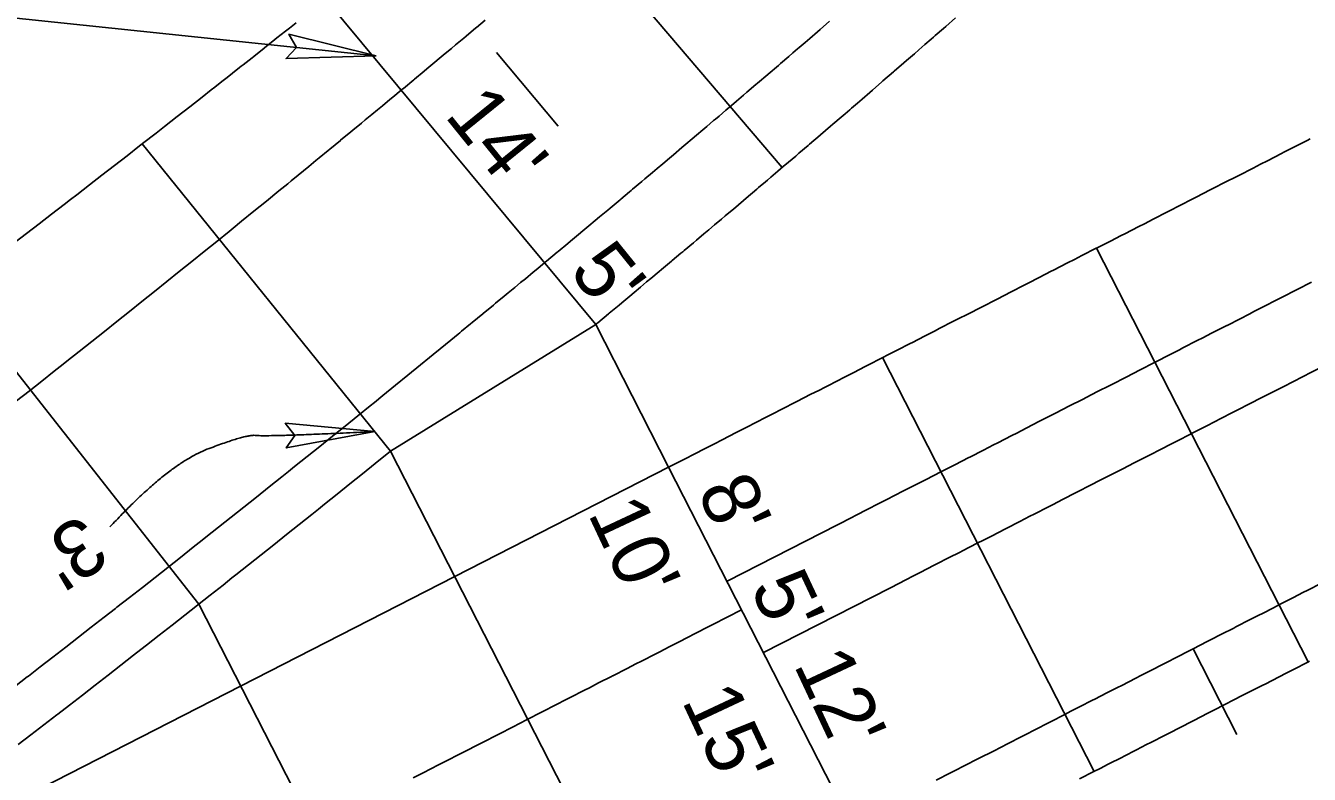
# Model space of a CAD drawing. Extents: x 2145147 to 2158018, y 137519 to 148068.
# Drawn here: x 2149836.3 to 2149916.4, y 143287.3 to 143334 of the extents above; entities that cross this region are included whole.
import ezdxf

# ---------------------------------------------------------------- set-up
doc = ezdxf.new("R2010")
doc.units = 0
for name, color, linetype in [('PR_Align_Ramp_A', 7, 'Continuous'), ('PR_Align_Ramp_F', 7, 'Continuous'), ('PR_Align_Service_C_Leader', 7, 'Continuous'), ('PR_Arrows', 7, 'Continuous'), ('PR_Dimensions', 7, 'Continuous'), ('PR_Joint_Contraction', 7, 'Continuous'), ('PR_Joint_Isolation', 7, 'Continuous'), ('PR_Joint_Long', 7, 'Continuous'), ('PR_Road_Concrete', 7, 'Continuous')]:
    doc.layers.add(name, color=color, linetype=linetype)

msp = doc.modelspace()

# ---------------------------------------------------------------- linework, layer by layer
at = {"layer": 'PR_Align_Ramp_A'}
msp.add_lwpolyline([(2149911.878, 143289.817), (2149909.145, 143295.159)], dxfattribs=at)
at = {"layer": 'PR_Align_Ramp_F'}
msp.add_lwpolyline([(2149869.527, 143327.778), (2149865.671, 143332.374)], dxfattribs=at)
at = {"layer": 'PR_Align_Service_C_Leader'}
msp.add_lwpolyline([(2149858.151, 143332.151), (2149826.935, 143335.418), (2149798.151, 143316.453)], dxfattribs=at)
at = {"layer": 'PR_Arrows'}
msp.add_lwpolyline([(2149858.151, 143332.151), (2149852.539, 143331.986), (2149853.191, 143332.67), (2149852.708, 143333.509)], close=True, dxfattribs=at)
at = {"layer": 'PR_Dimensions'}
msp.add_lwpolyline([(2149858.07, 143308.712), (2149852.548, 143307.7), (2149853.089, 143308.476), (2149852.484, 143309.232)], close=True, dxfattribs=at)
msp.add_open_spline([(2149841.542, 143302.766), (2149845.177, 143306.681), (2149850.08, 143308.559), (2149851.247, 143308.388), (2149858.07, 143308.712)], degree=2, dxfattribs=at)
at = {"layer": 'PR_Joint_Contraction'}
for p, q in [((2149883.51, 143325.197), (2149866.572, 143345.068)), ((2149859.056, 143307.493), (2149843.557, 143326.662)), ((2149903.123, 143320.16), (2149916.331, 143294.343)), ((2149847.09, 143297.948), (2149831.675, 143317.535)), ((2149889.769, 143313.328), (2149902.978, 143287.511)), ((2149859.056, 143307.493), (2149876.27, 143273.847)), ((2149847.09, 143297.948), (2149862.916, 143267.015))]:
    msp.add_line(p, q, dxfattribs=at)
at = {"layer": 'PR_Joint_Isolation'}
for p, q in [((2149871.861, 143315.398), (2149855.01, 143335.699)), ((2149876.415, 143306.496), (2149889.624, 143280.679))]:
    msp.add_line(p, q, dxfattribs=at)
at = {"layer": 'PR_Joint_Long'}
msp.add_line((2149876.415, 143306.497), (2149836.353, 143286.001), dxfattribs=at)
for points in [[(2149886.46, 143334.319), (2149885.872, 143333.811), (2149885.695, 143333.658), (2149885.22, 143333.248), (2149884.931, 143332.999), (2149884.568, 143332.687), (2149884.453, 143332.588), (2149884.165, 143332.34), (2149883.915, 143332.125), (2149883.4, 143331.682), (2149883.261, 143331.563), (2149882.633, 143331.025), (2149882.608, 143331.003), (2149881.957, 143330.446), (2149881.863, 143330.365), (2149881.303, 143329.886), (2149881.096, 143329.709), (2149880.648, 143329.327), (2149880.327, 143329.054), (2149879.992, 143328.768), (2149879.559, 143328.399), (2149879.338, 143328.211), (2149879.223, 143328.114), (2149878.789, 143327.745), (2149878.68, 143327.652), (2149878.027, 143327.098), (2149878.016, 143327.089), (2149877.37, 143326.542), (2149877.246, 143326.436), (2149876.713, 143325.985), (2149876.475, 143325.784), (2149876.055, 143325.429), (2149875.704, 143325.133), (2149875.397, 143324.874), (2149874.931, 143324.482), (2149874.738, 143324.319), (2149874.159, 143323.832), (2149874.08, 143323.766), (2149873.967, 143323.671), (2149873.423, 143323.214), (2149873.382, 143323.18), (2149872.763, 143322.661), (2149872.608, 143322.531), (2149872.103, 143322.108), (2149871.834, 143321.883), (2149871.442, 143321.556), (2149871.059, 143321.236), (2149870.781, 143321.004), (2149870.284, 143320.589), (2149870.119, 143320.452), (2149869.508, 143319.944), (2149869.457, 143319.902), (2149868.799, 143319.354), (2149868.729, 143319.297), (2149868.666, 143319.244), (2149868.136, 143318.804), (2149867.95, 143318.651), (2149867.473, 143318.255), (2149867.173, 143318.007), (2149866.809, 143317.706), (2149866.394, 143317.364), (2149866.145, 143317.158), (2149865.616, 143316.721), (2149865.48, 143316.61), (2149864.836, 143316.079), (2149864.816, 143316.063), (2149864.154, 143315.519), (2149864.053, 143315.435), (2149863.489, 143314.972), (2149863.377, 143314.881), (2149863.272, 143314.795), (2149862.822, 143314.426), (2149862.491, 143314.155), (2149862.156, 143313.881), (2149861.709, 143313.516), (2149861.489, 143313.336), (2149860.925, 143312.876), (2149860.143, 143312.238), (2149859.359, 143311.6), (2149858.575, 143310.964), (2149858.044, 143310.533), (2149857.788, 143310.326), (2149857.004, 143309.692), (2149856.217, 143309.057), (2149855.431, 143308.423), (2149854.644, 143307.789), (2149853.856, 143307.157), (2149853.068, 143306.525), (2149852.683, 143306.217), (2149852.277, 143305.892), (2149851.489, 143305.262), (2149850.699, 143304.632), (2149849.908, 143304.003), (2149849.117, 143303.374), (2149848.326, 143302.746), (2149847.535, 143302.12), (2149847.296, 143301.932), (2149846.74, 143301.492), (2149845.947, 143300.867), (2149845.154, 143300.241), (2149844.359, 143299.617), (2149843.564, 143298.993), (2149842.769, 143298.37), (2149841.975, 143297.749), (2149841.885, 143297.679), (2149841.176, 143297.126), (2149840.379, 143296.505), (2149839.581, 143295.885), (2149838.783, 143295.265), (2149837.985, 143294.646), (2149837.185, 143294.028), (2149836.452, 143293.461), (2149836.384, 143293.409), (2149835.585, 143292.793)], [(2149864.963, 143334.391), (2149864.422, 143333.937), (2149864.385, 143333.907), (2149863.771, 143333.391), (2149863.62, 143333.265), (2149863.119, 143332.846), (2149862.855, 143332.624), (2149862.467, 143332.3), (2149862.088, 143331.984), (2149861.814, 143331.756), (2149861.322, 143331.345), (2149861.161, 143331.212), (2149860.554, 143330.706), (2149860.508, 143330.668), (2149859.854, 143330.124), (2149859.787, 143330.069), (2149859.725, 143330.018), (2149859.2, 143329.581), (2149859.018, 143329.431), (2149858.545, 143329.039), (2149858.249, 143328.795), (2149857.89, 143328.498), (2149857.48, 143328.159), (2149857.235, 143327.956), (2149856.71, 143327.523), (2149856.579, 143327.416), (2149855.939, 143326.889), (2149855.923, 143326.875), (2149855.266, 143326.335), (2149855.168, 143326.255), (2149854.609, 143325.796), (2149854.5, 143325.706), (2149854.397, 143325.622), (2149853.951, 143325.257), (2149853.624, 143324.989), (2149853.293, 143324.718), (2149852.851, 143324.357), (2149852.635, 143324.181), (2149852.078, 143323.726), (2149851.304, 143323.095), (2149850.53, 143322.466), (2149849.755, 143321.836), (2149849.23, 143321.411), (2149848.979, 143321.208), (2149848.203, 143320.58), (2149847.426, 143319.953), (2149846.649, 143319.326), (2149845.872, 143318.7), (2149845.093, 143318.075), (2149844.314, 143317.451), (2149843.935, 143317.147), (2149843.535, 143316.827), (2149842.755, 143316.204), (2149841.975, 143315.582), (2149841.194, 143314.96), (2149840.412, 143314.339), (2149839.63, 143313.718), (2149838.847, 143313.099), (2149838.614, 143312.914), (2149838.064, 143312.48), (2149837.281, 143311.861), (2149836.496, 143311.244), (2149835.712, 143310.627)], [(2149916.536, 143318.036), (2149915.648, 143317.581), (2149915.561, 143317.537), (2149914.754, 143317.124), (2149914.094, 143316.786), (2149913.862, 143316.667), (2149912.983, 143316.218), (2149912.653, 143316.05), (2149912.083, 143315.757), (2149911.273, 143315.343), (2149911.261, 143315.337), (2149910.306, 143314.848), (2149909.752, 143314.565), (2149909.412, 143314.391), (2149908.513, 143313.931), (2149908.295, 143313.819), (2149907.642, 143313.485), (2149906.858, 143313.084), (2149906.75, 143313.03), (2149905.854, 143312.57), (2149905.406, 143312.341), (2149904.966, 143312.117), (2149904.07, 143311.658), (2149903.946, 143311.594), (2149903.186, 143311.206), (2149902.47, 143310.84), (2149902.278, 143310.74), (2149901.403, 143310.294), (2149901.03, 143310.103), (2149900.51, 143309.836), (2149899.608, 143309.375), (2149899.571, 143309.356), (2149898.73, 143308.926), (2149898.143, 143308.625), (2149897.845, 143308.473), (2149896.96, 143308.02), (2149896.695, 143307.885), (2149896.059, 143307.559), (2149895.206, 143307.123), (2149895.145, 143307.092), (2149894.28, 143306.649), (2149893.786, 143306.396), (2149893.394, 143306.196), (2149892.478, 143305.727), (2149892.322, 143305.647), (2149891.616, 143305.287), (2149890.867, 143304.903), (2149890.715, 143304.825), (2149889.827, 143304.371), (2149889.416, 143304.161), (2149888.94, 143303.917), (2149888.004, 143303.439), (2149887.923, 143303.397), (2149880.059, 143299.373)], [(2149871.861, 143315.398), (2149859.056, 143307.493), (2149858.101, 143306.722), (2149857.312, 143306.086), (2149856.523, 143305.451), (2149855.733, 143304.817), (2149854.943, 143304.183), (2149854.557, 143303.874), (2149854.152, 143303.55), (2149853.361, 143302.918), (2149852.568, 143302.286), (2149851.776, 143301.655), (2149850.983, 143301.025), (2149850.189, 143300.395), (2149849.395, 143299.766), (2149849.158, 143299.579), (2149848.6, 143299.138), (2149847.805, 143298.511), (2149847.009, 143297.884), (2149846.212, 143297.258), (2149845.415, 143296.632), (2149844.618, 143296.008), (2149843.82, 143295.383), (2149843.733, 143295.316), (2149843.021, 143294.76), (2149842.222, 143294.137), (2149841.422, 143293.516), (2149840.622, 143292.894), (2149839.821, 143292.274), (2149839.02, 143291.654), (2149838.282, 143291.085), (2149838.218, 143291.035), (2149837.415, 143290.416), (2149836.612, 143289.799), (2149835.809, 143289.182)], [(2149917.032, 143312.673), (2149916.374, 143312.336), (2149916.141, 143312.217), (2149915.258, 143311.766), (2149914.931, 143311.598), (2149914.361, 143311.306), (2149913.529, 143310.881), (2149913.519, 143310.876), (2149912.583, 143310.396), (2149912.028, 143310.113), (2149911.69, 143309.94), (2149910.794, 143309.481), (2149910.573, 143309.368), (2149909.917, 143309.033), (2149909.132, 143308.631), (2149909.026, 143308.577), (2149908.131, 143308.119), (2149907.68, 143307.888), (2149907.242, 143307.665), (2149906.348, 143307.207), (2149906.222, 143307.142), (2149905.462, 143306.754), (2149904.754, 143306.392), (2149904.559, 143306.291), (2149903.68, 143305.842), (2149903.31, 143305.653), (2149902.788, 143305.385), (2149901.89, 143304.926), (2149901.853, 143304.907), (2149901.008, 143304.475), (2149900.418, 143304.173), (2149900.121, 143304.021), (2149899.235, 143303.567), (2149898.969, 143303.432), (2149898.337, 143303.108), (2149897.491, 143302.676), (2149897.43, 143302.644), (2149896.557, 143302.198), (2149896.062, 143301.944), (2149895.67, 143301.744), (2149894.762, 143301.279), (2149894.602, 143301.197), (2149893.892, 143300.835), (2149893.147, 143300.453), (2149892.994, 143300.375), (2149892.105, 143299.92), (2149891.696, 143299.711), (2149891.217, 143299.466), (2149890.294, 143298.994), (2149890.215, 143298.953), (2149882.337, 143294.922)], [(2149917.158, 143299.258), (2149916.267, 143298.802), (2149916.041, 143298.686), (2149915.377, 143298.347), (2149914.589, 143297.944), (2149914.487, 143297.892), (2149913.597, 143297.436), (2149913.137, 143297.201), (2149912.706, 143296.981), (2149911.816, 143296.525), (2149911.685, 143296.458), (2149910.926, 143296.07), (2149910.234, 143295.716), (2149910.036, 143295.614), (2149909.145, 143295.159), (2149908.782, 143294.973), (2149908.255, 143294.703), (2149907.365, 143294.248), (2149907.33, 143294.23), (2149906.474, 143293.792), (2149905.878, 143293.487), (2149905.584, 143293.337), (2149904.694, 143292.881), (2149904.427, 143292.745), (2149903.804, 143292.426), (2149902.975, 143292.002), (2149902.913, 143291.97), (2149902.023, 143291.515), (2149901.523, 143291.259), (2149901.133, 143291.06), (2149900.243, 143290.604), (2149900.072, 143290.516), (2149899.352, 143290.149), (2149898.62, 143289.774), (2149898.462, 143289.693), (2149897.572, 143289.238), (2149897.168, 143289.031), (2149896.682, 143288.782), (2149895.791, 143288.327), (2149895.716, 143288.288), (2149894.901, 143287.871), (2149894.265, 143287.546), (2149894.011, 143287.416), (2149893.121, 143286.96)], [(2149880.97, 143297.594), (2149879.167, 143296.67), (2149878.722, 143296.443), (2149878.276, 143296.215), (2149877.386, 143295.759), (2149877.27, 143295.7), (2149876.496, 143295.304), (2149875.819, 143294.958), (2149875.606, 143294.849), (2149874.715, 143294.393), (2149874.367, 143294.215), (2149873.825, 143293.938), (2149872.935, 143293.482), (2149872.915, 143293.472), (2149872.851, 143293.439), (2149872.045, 143293.027), (2149871.464, 143292.729), (2149871.154, 143292.571), (2149870.264, 143292.116), (2149870.012, 143291.987), (2149869.374, 143291.66), (2149868.56, 143291.244), (2149868.484, 143291.205), (2149867.593, 143290.749), (2149867.108, 143290.501), (2149866.703, 143290.294), (2149865.813, 143289.838), (2149865.657, 143289.758), (2149864.923, 143289.383), (2149864.205, 143289.016), (2149864.032, 143288.927), (2149863.142, 143288.472), (2149862.753, 143288.273), (2149862.252, 143288.017), (2149861.362, 143287.561), (2149861.301, 143287.53), (2149860.471, 143287.106)]]:
    msp.add_lwpolyline(points, dxfattribs=at)
at = {"layer": 'PR_Road_Concrete'}
msp.add_line((2149871.861, 143315.398), (2149876.415, 143306.497), dxfattribs=at)
for points in [[(2149853.159, 143334.222), (2149852.745, 143333.893), (2149852.498, 143333.696), (2149851.968, 143333.276), (2149851.836, 143333.171), (2149851.191, 143332.659), (2149851.174, 143332.646), (2149850.512, 143332.121), (2149850.414, 143332.044), (2149849.85, 143331.598), (2149849.74, 143331.511), (2149849.636, 143331.429), (2149849.187, 143331.074), (2149848.857, 143330.814), (2149848.523, 143330.551), (2149848.078, 143330.201), (2149847.86, 143330.029), (2149847.298, 143329.588), (2149846.518, 143328.975), (2149845.737, 143328.364), (2149844.956, 143327.753), (2149844.426, 143327.34), (2149844.174, 143327.143), (2149843.391, 143326.533), (2149842.609, 143325.924), (2149841.825, 143325.316), (2149841.041, 143324.709), (2149840.257, 143324.102), (2149839.472, 143323.496), (2149839.089, 143323.201), (2149838.686, 143322.891), (2149837.901, 143322.286), (2149837.114, 143321.682), (2149836.327, 143321.079), (2149835.54, 143320.476)], [(2149894.327, 143334.532), (2149893.707, 143333.991), (2149893.562, 143333.865), (2149893.056, 143333.423), (2149892.94, 143333.322), (2149892.797, 143333.198), (2149892.404, 143332.856), (2149892.032, 143332.532), (2149891.752, 143332.289), (2149891.265, 143331.866), (2149891.099, 143331.722), (2149890.499, 143331.202), (2149890.446, 143331.156), (2149889.793, 143330.591), (2149889.731, 143330.537), (2149889.139, 143330.026), (2149888.963, 143329.874), (2149888.485, 143329.461), (2149888.195, 143329.211), (2149887.83, 143328.897), (2149887.715, 143328.798), (2149887.426, 143328.549), (2149887.175, 143328.333), (2149886.656, 143327.888), (2149886.519, 143327.77), (2149885.886, 143327.227), (2149885.863, 143327.208), (2149885.207, 143326.646), (2149885.115, 143326.567), (2149884.55, 143326.084), (2149884.343, 143325.908), (2149883.893, 143325.523), (2149883.571, 143325.249), (2149883.235, 143324.962), (2149882.799, 143324.591), (2149882.577, 143324.402), (2149882.463, 143324.305), (2149882.026, 143323.934), (2149881.918, 143323.842), (2149881.259, 143323.283), (2149881.252, 143323.277), (2149880.6, 143322.725), (2149880.478, 143322.621), (2149879.94, 143322.166), (2149879.703, 143321.965), (2149879.28, 143321.609), (2149878.927, 143321.311), (2149878.62, 143321.051), (2149878.151, 143320.657), (2149877.959, 143320.495), (2149877.375, 143320.004), (2149877.297, 143319.938), (2149877.184, 143319.844), (2149876.635, 143319.383), (2149876.597, 143319.351), (2149875.973, 143318.827), (2149875.82, 143318.699), (2149875.31, 143318.273), (2149875.041, 143318.048), (2149874.647, 143317.718), (2149874.263, 143317.397), (2149873.984, 143317.165), (2149873.483, 143316.747), (2149873.32, 143316.611), (2149872.703, 143316.098), (2149872.656, 143316.058), (2149871.991, 143315.506), (2149871.923, 143315.449), (2149871.879, 143315.413)], [(2149916.454, 143326.98), (2149916.268, 143326.885), (2149915.564, 143326.524), (2149914.816, 143326.142), (2149914.673, 143326.069), (2149913.783, 143325.613), (2149913.364, 143325.399), (2149912.893, 143325.158), (2149912.003, 143324.702), (2149911.913, 143324.656), (2149911.112, 143324.247), (2149910.461, 143323.914), (2149910.222, 143323.792), (2149909.332, 143323.336), (2149909.009, 143323.171), (2149908.442, 143322.881), (2149907.557, 143322.428), (2149907.551, 143322.425), (2149906.661, 143321.97), (2149906.106, 143321.685), (2149905.771, 143321.514), (2149904.881, 143321.059), (2149904.654, 143320.943), (2149903.99, 143320.603), (2149903.202, 143320.2), (2149903.1, 143320.148), (2149902.21, 143319.692), (2149901.75, 143319.457), (2149901.32, 143319.237), (2149900.429, 143318.781), (2149900.299, 143318.715), (2149899.539, 143318.326), (2149898.847, 143317.972), (2149898.649, 143317.87), (2149897.759, 143317.415), (2149897.395, 143317.229), (2149896.868, 143316.96), (2149895.978, 143316.504), (2149895.944, 143316.486), (2149895.088, 143316.049), (2149894.492, 143315.744), (2149894.198, 143315.593), (2149893.307, 143315.138), (2149893.04, 143315.001), (2149892.417, 143314.682), (2149891.588, 143314.258), (2149891.527, 143314.227), (2149890.637, 143313.771), (2149890.137, 143313.516), (2149889.746, 143313.316), (2149888.856, 143312.86), (2149888.685, 143312.773), (2149887.966, 143312.405), (2149887.233, 143312.03), (2149887.076, 143311.949), (2149886.185, 143311.494), (2149885.781, 143311.287), (2149885.295, 143311.039), (2149884.405, 143310.583), (2149884.33, 143310.545), (2149883.515, 143310.128), (2149882.878, 143309.802), (2149882.624, 143309.672), (2149881.734, 143309.217), (2149881.426, 143309.059), (2149880.844, 143308.761), (2149879.974, 143308.316), (2149879.954, 143308.306), (2149879.063, 143307.85), (2149878.523, 143307.574), (2149878.173, 143307.395), (2149877.283, 143306.939), (2149877.071, 143306.831), (2149876.415, 143306.496)], [(2149916.411, 143294.383), (2149916.309, 143294.33), (2149915.418, 143293.875), (2149914.959, 143293.64), (2149914.528, 143293.42), (2149913.638, 143292.964), (2149913.507, 143292.897), (2149912.748, 143292.509), (2149912.055, 143292.155), (2149911.857, 143292.053), (2149910.967, 143291.598), (2149910.604, 143291.412), (2149910.077, 143291.142), (2149909.187, 143290.687), (2149909.152, 143290.669), (2149908.296, 143290.231), (2149907.7, 143289.926), (2149907.406, 143289.776), (2149906.516, 143289.32), (2149906.249, 143289.184), (2149905.626, 143288.865), (2149904.797, 143288.441), (2149904.735, 143288.409), (2149903.845, 143287.954), (2149903.345, 143287.698), (2149902.955, 143287.498), (2149902.065, 143287.043)]]:
    msp.add_lwpolyline(points, dxfattribs=at)

# ---------------------------------------------------------------- texts
at = {"layer": 'PR_Dimensions'}
for s, rotation, p in [("14'", 308.92962, (2149862.372, 143328.418)), ("5'", 308.92962, (2149870.133, 143318.69)), ("8'", 295.10211, (2149878.152, 143304.997)), ("10'", 295.10211, (2149871.343, 143303.613)), ("3'", 212.89821, (2149839.772, 143303.646)), ("5'", 295.10211, (2149881.468, 143298.982)), ("12'", 295.10211, (2149884.189, 143294.176)), ("15'", 295.10211, (2149877.201, 143291.928))]:
    msp.add_text(s, height=3.6, rotation=rotation, dxfattribs=at).set_placement(p)

doc.saveas('drawing.dxf')
